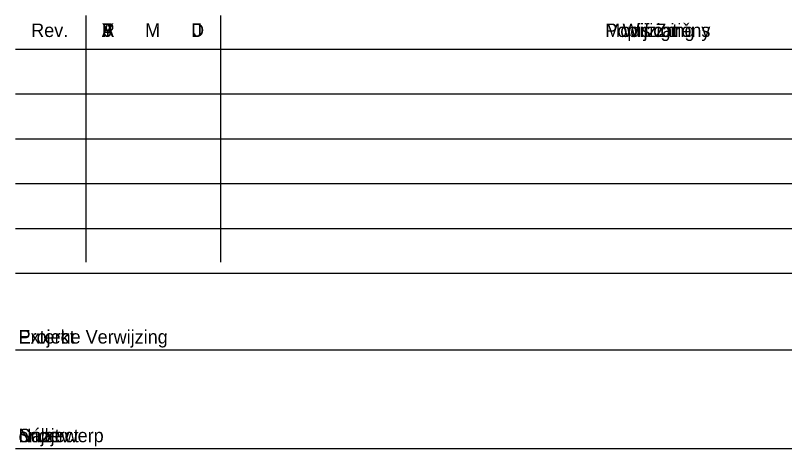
# Model space of a CAD drawing. Extents: x -760612 to 2731, y -975740 to 2995.
# Drawn here: x 727 to 1584, y 1100 to 1583 of the extents above; entities that cross this region are included whole.
import ezdxf

# ---------------------------------------------------------------- set-up
doc = ezdxf.new("R2010")
doc.units = 0
for name, color, linetype in [('Border', 7, 'Continuous'), ('Border_TextCZ', 7, 'Continuous'), ('Border_TextFR', 7, 'Continuous'), ('Border_TextNL', 7, 'Continuous'), ('Border_TextUK', 7, 'Continuous')]:
    doc.layers.add(name, color=color, linetype=linetype)

# ---------------------------------------------------------------- blocks, each defined once
blk = doc.blocks.new('A3coversheet_v03_CZ_1_1')
at = {"layer": 'Border'}
blk.add_line((2.19583, 1.52058), (4.09583, 1.52058), dxfattribs=at)
for points in [[(2.27417, 1.55808), (2.27417, 1.28308)], [(2.42417, 1.55808), (2.42417, 1.28308)], [(2.19583, 1.52058), (4.10417, 1.52058)], [(2.19583, 1.47058), (4.10417, 1.47058)], [(2.19583, 1.42058), (4.10417, 1.42058)], [(2.19583, 1.37058), (4.10417, 1.37058)], [(2.19583, 1.32058), (4.10417, 1.32058)], [(2.19583, 1.27058), (4.10417, 1.27058)], [(2.19583, 1.18503), (4.10417, 1.18503)], [(2.19583, 1.07503), (4.10417, 1.07503)]]:
    blk.add_lwpolyline(points, dxfattribs=at)
at = {"layer": 'Border_TextCZ'}
for s, p in [('Rev.', (2.21345, 1.53396)), ('R', (2.29212, 1.5341)), ('M', (2.34039, 1.5341)), ('D', (2.39155, 1.5341)), ('Popis Změny', (2.85302, 1.53396)), ('Projekt', (2.19942, 1.19219)), ('Název', (2.19942, 1.08219))]:
    blk.add_text(s, height=0.015, dxfattribs=at).set_placement(p)
at = {"layer": 'Border_TextFR'}
for s, p in [('Rev.', (2.21345, 1.53396)), ('A', (2.29212, 1.5341)), ('M', (2.34039, 1.5341)), ('J', (2.39388, 1.5341)), ('Modifications', (2.85301, 1.53396)), ('Projet', (2.19942, 1.19219)), ('Sujet', (2.19942, 1.08219))]:
    blk.add_text(s, height=0.015, dxfattribs=at).set_placement(p)
at = {"layer": 'Border_TextNL'}
for s, p in [('Rev.', (2.21345, 1.53396)), ('J', (2.29388, 1.5341)), ('M', (2.34039, 1.5341)), ('D', (2.39155, 1.5341)), ('Wijziging', (2.87223, 1.53396)), ('Externe Verwijzing', (2.19942, 1.19219)), ('onderwerp', (2.19942, 1.08219))]:
    blk.add_text(s, height=0.015, dxfattribs=at).set_placement(p)
at = {"layer": 'Border_TextUK'}
for s, p in [('Rev.', (2.21345, 1.53396)), ('Y', (2.29212, 1.5341)), ('M', (2.34039, 1.5341)), ('D', (2.39155, 1.5341)), ('Modifications', (2.85301, 1.53396)), ('Project', (2.19942, 1.19219)), ('Subject', (2.19942, 1.08219))]:
    blk.add_text(s, height=0.015, dxfattribs=at).set_placement(p)

msp = doc.modelspace()

# ---------------------------------------------------------------- block references
at = {"layer": 'Border', "xscale": 1000.0000004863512, "yscale": 1000.0000004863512, "rotation": 4.518606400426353e-10}
msp.add_blockref('A3coversheet_v03_CZ_1_1', (-1469, 25), dxfattribs=at)

doc.saveas('drawing.dxf')
